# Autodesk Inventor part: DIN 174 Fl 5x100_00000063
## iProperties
Created: 2006-03
Part Number: DIN 174 Fl 5x100_00000063
Material: Default
Document SubType Name: Modeling
Designer: Carlo
Stock Number: DIN 174 Fl 5x100
Mass: 881.349 g
Surface Area: 3712.08 cm^2
Volume: 881.349 cm^3
Density: 1 g/cm^3
G_L: 1762.896 mm
G_W: 5.000 mm
G_H: 100.000 mm
AFG_Item: 100 x 5
CSToolsMass: 1.0
CSToolsVolume: 881349.0
CSToolsArea: 3712.0
Author: Carlo
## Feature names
1. AFG_Detailed_DIN 174 Fl 5x100_00000063 [Extrusion]
2. AFG_Simplified_DIN 174 Fl 5x100_00000063 [Extrusion]
3. AFG_StartExtrusion_1 [Extrusion]
4. AFG_StartExtrusion_2 [Extrusion]
5. AFG_EndExtrusion_1 [Extrusion]
6. AFG_EndExtrusion_2 [Extrusion]
